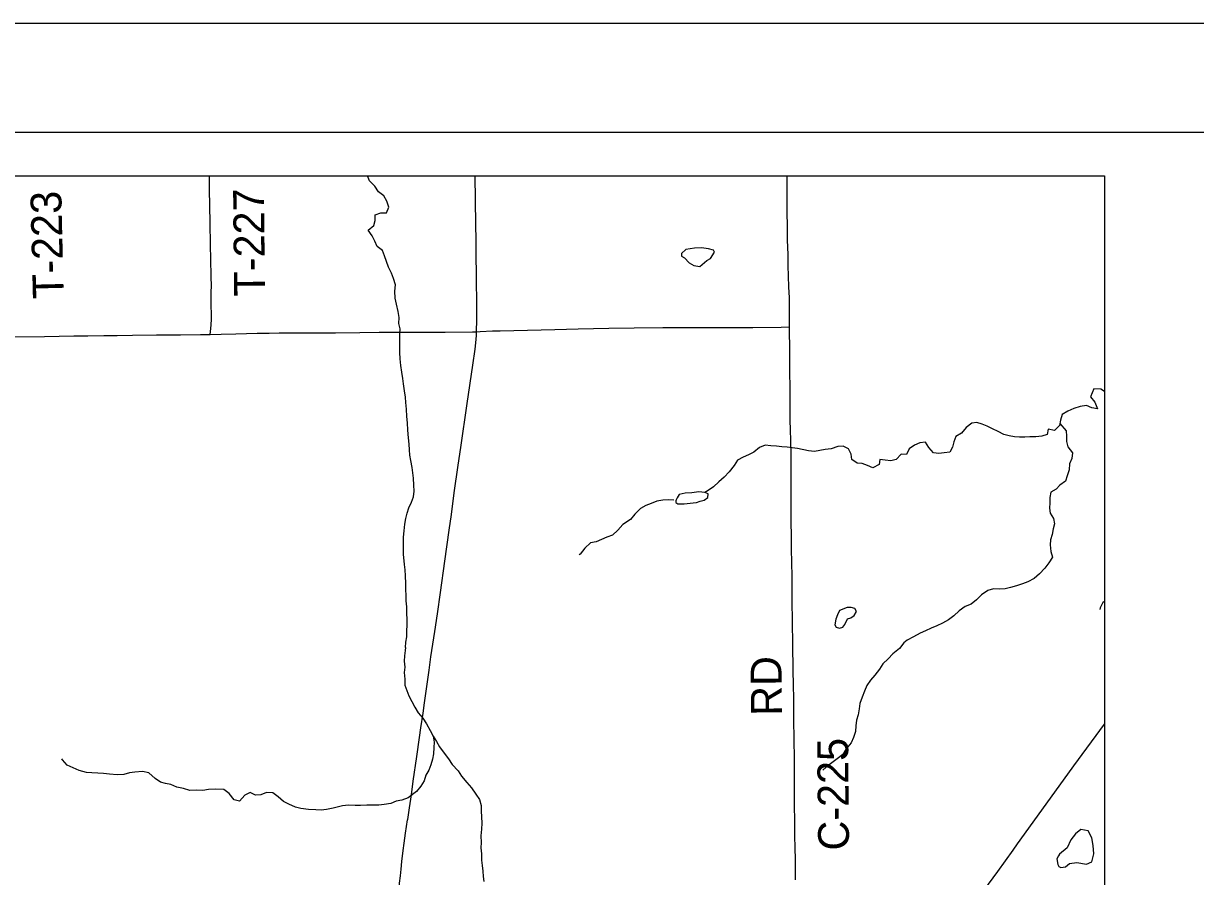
# Model space of a CAD drawing. Extents: x 0 to 34, y 0 to 22.
# Drawn here: x 13.7 to 19.09, y 18.08 to 22 of the extents above; entities that cross this region are included whole.
import ezdxf

# ---------------------------------------------------------------- set-up
doc = ezdxf.new("R2010")
doc.units = 0
for name, color, linetype in [('GM_X_County_Road', 7, 'Continuous'), ('GM_X_County_Road_Text', 7, 'Continuous'), ('GM_X_Minor_Lake', 7, 'Continuous'), ('GM_X_Minor_River', 7, 'Continuous'), ('GM_X_State_Route', 7, 'Continuous'), ('GM_X_Township_Road', 7, 'Continuous'), ('GM_X_Township_Road_Text', 7, 'Continuous'), ('SH_Border', 7, 'Continuous'), ('SH_Cut_Line', 7, 'Continuous'), ('SH_Text', 7, 'Continuous')]:
    doc.layers.add(name, color=color, linetype=linetype)

msp = doc.modelspace()

# ---------------------------------------------------------------- linework, layer by layer
at = {"layer": 'GM_X_County_Road'}
for points in [[(17.2229, 20.6048), (17.2225, 20.7377), (17.2203, 20.7889), (17.2177, 20.8865), (17.2166, 20.9377), (17.2146, 21.0029), (17.2126, 21.1958), (17.2123, 21.2549), (17.2117, 21.2991)], [(15.7844, 20.5828), (15.8012, 20.5841), (15.857, 20.5859), (15.8927, 20.5867), (16.1444, 20.5934), (16.2515, 20.5958), (16.3928, 20.5995), (16.5093, 20.6011), (16.6413, 20.6017), (16.719, 20.6015), (16.8278, 20.6021), (16.8945, 20.6018), (17.0546, 20.6022), (17.1851, 20.6042), (17.2229, 20.6048)], [(17.2505, 18.0622), (17.2503, 18.1617), (17.2489, 18.2036), (17.2481, 18.2704), (17.2459, 18.4677), (17.2458, 18.5065), (17.2463, 18.6104), (17.2447, 18.716), (17.2434, 18.7921), (17.2425, 18.9008), (17.2415, 18.9521), (17.2405, 19.0313), (17.2388, 19.14), (17.2371, 19.2534), (17.236, 19.342), (17.2347, 19.4646), (17.2346, 19.5143), (17.2327, 19.5904), (17.2306, 19.7611), (17.2312, 19.8154), (17.2309, 19.8496), (17.2309, 19.8899), (17.2305, 20.016), (17.2286, 20.0872), (17.2278, 20.1275), (17.2267, 20.1803), (17.2263, 20.2331), (17.2259, 20.3092), (17.2248, 20.4133), (17.2242, 20.4877), (17.2229, 20.6048)], [(13.6426, 20.5582), (13.6588, 20.5587), (13.7969, 20.5609), (13.9321, 20.5629), (13.9973, 20.5638), (14.0703, 20.5652), (14.1324, 20.5657), (14.2022, 20.567), (14.3125, 20.5687), (14.4228, 20.569), (14.5144, 20.5703), (14.5517, 20.5702), (14.5597, 20.5702)], [(14.5597, 20.5702), (14.6106, 20.5707), (14.6773, 20.5736), (14.7748, 20.5755), (14.8306, 20.5766), (14.8772, 20.5768), (14.9486, 20.5773), (15.0121, 20.5775), (15.0741, 20.5778), (15.1362, 20.5779), (15.2481, 20.5792), (15.3367, 20.5804), (15.3708, 20.5805), (15.4298, 20.58), (15.565, 20.5809), (15.6396, 20.581), (15.7659, 20.5825), (15.7844, 20.5828)]]:
    msp.add_lwpolyline(points, dxfattribs=at)
at = {"layer": 'GM_X_Minor_Lake'}
for p, q in [((16.7405, 20.9221), (16.7624, 20.8994)), ((16.739, 19.7912), (16.7807, 19.7962)), ((17.4778, 19.2361), (17.49, 19.2628))]:
    msp.add_line(p, q, dxfattribs=at)
for points in [[(16.7624, 20.8994), (16.7833, 20.8871), (16.8109, 20.8825), (16.8213, 20.8911), (16.843, 20.9102), (16.86, 20.9188), (16.8779, 20.9484), (16.8732, 20.9579), (16.8504, 20.9644), (16.819, 20.9681), (16.7858, 20.9669), (16.746, 20.9601), (16.7271, 20.9429), (16.7262, 20.9305), (16.7405, 20.9221)], [(16.7807, 19.7962), (16.7958, 19.7981), (16.812, 19.803), (16.8309, 19.8078), (16.8479, 19.8202), (16.8498, 19.8374), (16.8345, 19.8439), (16.807, 19.8457), (16.7738, 19.8417), (16.7435, 19.8397), (16.716, 19.8348), (16.7066, 19.8195), (16.7019, 19.81), (16.7009, 19.8053), (16.701, 19.7977), (16.7095, 19.791), (16.7295, 19.7911), (16.739, 19.7912)], [(17.49, 19.2628), (17.5051, 19.2676), (17.5212, 19.2772), (17.5306, 19.2963), (17.5239, 19.3105), (17.5068, 19.3151), (17.4888, 19.3141), (17.4537, 19.3006), (17.4443, 19.2806), (17.4368, 19.2616), (17.4313, 19.2349), (17.438, 19.2236), (17.4532, 19.2189), (17.4683, 19.2247), (17.4778, 19.2361)], [(18.4707, 18.1186), (18.4926, 18.1227), (18.5105, 18.1381), (18.5437, 18.1422), (18.5893, 18.1342), (18.6138, 18.1458), (18.623, 18.182), (18.6188, 18.2199), (18.6137, 18.255), (18.5972, 18.2881), (18.5621, 18.2934), (18.5376, 18.2742), (18.517, 18.2464), (18.5003, 18.2092), (18.4653, 18.1803)], [(18.4653, 18.1803), (18.4606, 18.1726), (18.4523, 18.1583), (18.4563, 18.1336), (18.4621, 18.1233), (18.4707, 18.1186)]]:
    msp.add_lwpolyline(points, dxfattribs=at)
at = {"layer": 'GM_X_Minor_River'}
for points in [[(15.4582, 19.131), (15.459, 19.1557), (15.4636, 19.1795), (15.4635, 19.2061), (15.4653, 19.2346), (15.4652, 19.2593), (15.4641, 19.2878), (15.463, 19.3182), (15.461, 19.3458), (15.4599, 19.3714), (15.4589, 19.3952), (15.4587, 19.4256), (15.4576, 19.4607), (15.4556, 19.4873), (15.4526, 19.513), (15.4486, 19.5595), (15.4476, 19.5842), (15.4484, 19.6146), (15.4483, 19.6384), (15.4519, 19.6669), (15.4547, 19.6973), (15.4593, 19.724), (15.4649, 19.7487), (15.4733, 19.7725), (15.4846, 19.7982), (15.4939, 19.823), (15.4967, 19.8496), (15.4965, 19.8771), (15.4945, 19.9094), (15.4915, 19.9332), (15.4876, 19.9579), (15.4818, 19.9902), (15.4779, 20.0148), (15.4759, 20.0395), (15.4748, 20.0661), (15.4718, 20.0946), (15.4688, 20.1298), (15.4668, 20.163), (15.4638, 20.1925), (15.4617, 20.2267), (15.4597, 20.2571), (15.4568, 20.2818), (15.4528, 20.3112), (15.4489, 20.3435), (15.4459, 20.3682), (15.441, 20.3967), (15.4362, 20.4271), (15.4332, 20.4584), (15.4312, 20.4869), (15.432, 20.5135), (15.4318, 20.543), (15.4308, 20.5724), (15.4326, 20.5962), (15.4267, 20.6209), (15.4285, 20.6475), (15.4237, 20.676), (15.4159, 20.7092), (15.4101, 20.7367), (15.409, 20.769), (15.4108, 20.7985), (15.403, 20.827), (15.3925, 20.8516), (15.38, 20.8791), (15.3695, 20.9057), (15.3608, 20.9313), (15.3522, 20.9559), (15.3274, 20.9748), (15.3169, 20.9995), (15.3044, 21.0241), (15.2863, 21.0488), (15.3118, 21.0707), (15.3174, 21.0945), (15.3182, 21.1202), (15.3448, 21.1298), (15.3694, 21.129), (15.3816, 21.1547), (15.372, 21.1822), (15.3577, 21.2069), (15.3339, 21.2257), (15.3167, 21.2513), (15.2919, 21.2759), (15.2829, 21.2991)], [(18.6712, 20.3073), (18.6546, 20.3178), (18.6224, 20.3194), (18.6075, 20.2832), (18.6266, 20.2586), (18.6392, 20.2283), (18.6136, 20.2329), (18.5888, 20.2441), (18.5595, 20.2391), (18.5302, 20.2293), (18.5027, 20.2177), (18.4773, 20.2023), (18.4699, 20.1766), (18.4653, 20.1518), (18.4418, 20.1279)], [(18.4418, 20.1279), (18.4121, 20.1341), (18.4084, 20.1103), (18.3838, 20.1016), (18.3553, 20.0996), (18.3288, 20.0994), (18.305, 20.0984), (18.2813, 20.0983), (18.2576, 20.1), (18.2329, 20.1037), (18.2082, 20.1093), (18.1825, 20.1244), (18.1559, 20.1356), (18.1321, 20.1479), (18.1084, 20.1582), (18.0846, 20.1657), (18.0609, 20.1618), (18.0354, 20.1417), (18.0137, 20.1169), (17.9881, 20.1015), (17.9787, 20.0768), (17.9732, 20.0521), (17.96, 20.0282), (17.9344, 20.0253), (17.9097, 20.0232), (17.885, 20.025), (17.8631, 20.0496), (17.8478, 20.0742), (17.8232, 20.0713), (17.7985, 20.0607), (17.7739, 20.0434), (17.7608, 20.0187), (17.737, 20.0195), (17.7134, 19.9956), (17.6888, 19.9889), (17.6632, 19.9916), (17.6385, 19.9953), (17.6348, 19.9715), (17.6064, 19.9571), (17.5817, 19.9674), (17.5579, 19.9759), (17.5342, 19.9786), (17.5104, 19.9946), (17.5074, 20.0193), (17.494, 20.044), (17.4693, 20.0562), (17.4456, 20.0542), (17.4143, 20.0445), (17.3878, 20.0415), (17.3631, 20.0357), (17.3375, 20.0318), (17.3109, 20.0345), (17.2597, 20.0456), (17.2359, 20.0493), (17.2122, 20.052), (17.1875, 20.0538), (17.1628, 20.0565), (17.1372, 20.0583), (17.1116, 20.061), (17.0851, 20.0495), (17.0595, 20.0285), (17.0349, 20.016), (17.0094, 20.0054), (16.9847, 19.992), (16.9687, 19.9682), (16.9461, 19.9386), (16.9225, 19.9137), (16.8979, 19.8927), (16.8733, 19.8688), (16.8487, 19.8526), (16.8346, 19.843)], [(18.4669, 20.1603), (18.4949, 20.1264), (18.497, 20.1027), (18.4963, 20.078), (18.5031, 20.0533), (18.5242, 20.025), (18.5215, 20.0003), (18.5113, 19.9745), (18.5087, 19.9479), (18.4994, 19.9203), (18.493, 19.8955), (18.4666, 19.8772), (18.4494, 19.8587)], [(18.4494, 19.8587), (18.4248, 19.8452), (18.4202, 19.8196), (18.4203, 19.7958), (18.4185, 19.772), (18.4224, 19.7483), (18.4367, 19.7237), (18.4416, 19.6999), (18.436, 19.6762), (18.4314, 19.6505), (18.4239, 19.6257), (18.4211, 19.602), (18.4251, 19.5716), (18.4318, 19.5459), (18.4158, 19.5202), (18.397, 19.4954), (18.3734, 19.4687), (18.3488, 19.4476), (18.3194, 19.4332), (18.2948, 19.4236), (18.2664, 19.4149), (18.2399, 19.4062), (18.2152, 19.4004), (18.1867, 19.3993), (18.1611, 19.4001), (18.1346, 19.3934), (18.1062, 19.3733), (18.0826, 19.3494), (18.058, 19.3293), (18.0306, 19.3187), (18.0031, 19.2986), (17.9786, 19.2766), (17.954, 19.2585), (17.9265, 19.2422), (17.9, 19.2297), (17.8744, 19.2191), (17.8489, 19.2076), (17.8243, 19.196), (17.793, 19.1797), (17.7646, 19.1639)], [(16.6914, 19.8081), (16.6658, 19.8089), (16.6411, 19.8078), (16.6137, 19.8029), (16.5871, 19.7923), (16.5625, 19.7837), (16.5379, 19.7693), (16.5114, 19.7444), (16.4916, 19.7196), (16.4576, 19.6957), (16.434, 19.6709), (16.4094, 19.6479), (16.3838, 19.6383), (16.3583, 19.6268), (16.3336, 19.6162), (16.308, 19.6123), (16.2825, 19.5874), (16.2599, 19.5598), (16.2561, 19.556)], [(18.6712, 19.3373), (18.6652, 19.3401), (18.6512, 19.3134), (18.6503, 19.3048)], [(17.7646, 19.1639), (17.7491, 19.1527), (17.7286, 19.1259), (17.6985, 19.1018), (17.6761, 19.0778), (17.6517, 19.0557), (17.6368, 19.0308), (17.6154, 19.004), (17.5957, 18.98), (17.579, 18.9552), (17.5679, 18.9294), (17.5568, 18.9017), (17.5467, 18.8731), (17.5432, 18.8484), (17.5388, 18.8218), (17.5315, 18.797), (17.5289, 18.7704), (17.5264, 18.7447), (17.5172, 18.7161), (17.5061, 18.6923), (17.4837, 18.6654), (17.4679, 18.6387), (17.4416, 18.6184), (17.4172, 18.6001), (17.3919, 18.5799), (17.3769, 18.5664)], [(15.4582, 19.131), (15.4562, 19.1174), (15.4527, 19.0919), (15.4511, 19.0672), (15.4542, 19.0406), (15.4516, 19.015), (15.4548, 18.9846), (15.4551, 18.958), (15.463, 18.9334), (15.4736, 18.9089), (15.4872, 18.8825), (15.4998, 18.856), (15.5152, 18.8296), (15.5373, 18.8052), (15.5546, 18.7798), (15.571, 18.7496), (15.5855, 18.7232), (15.6, 18.6986), (15.6145, 18.6732), (15.6356, 18.6449), (15.6549, 18.6195), (15.6722, 18.5931), (15.699, 18.564), (15.7145, 18.5395), (15.7394, 18.5104), (15.7615, 18.485), (15.7807, 18.4567), (15.7971, 18.4322), (15.805, 18.4038), (15.8062, 18.3782), (15.8065, 18.3526), (15.8087, 18.3232), (15.8071, 18.2956), (15.8046, 18.2643), (15.805, 18.2339), (15.8043, 18.2092), (15.8065, 18.1826), (15.8077, 18.1532), (15.8099, 18.1276), (15.813, 18.102), (15.8152, 18.0783), (15.8183, 18.0546)], [(15.5855, 18.7232), (15.5896, 18.6957), (15.588, 18.671), (15.5864, 18.6415), (15.581, 18.6177), (15.5747, 18.5911), (15.5655, 18.5672), (15.5516, 18.5433), (15.5433, 18.5176), (15.5275, 18.4937), (15.5079, 18.4678), (15.4703, 18.4398), (15.4401, 18.429), (15.4146, 18.424), (15.3901, 18.4133), (15.3589, 18.4082), (15.3343, 18.406), (15.3088, 18.4057), (15.2794, 18.4063), (15.251, 18.4041), (15.2264, 18.4047), (15.1952, 18.4053), (15.1677, 18.4021), (15.1252, 18.3922), (15.095, 18.3861), (15.0704, 18.383), (15.0458, 18.3846), (15.0117, 18.3851), (14.9766, 18.3904), (14.9519, 18.3968), (14.9205, 18.4097), (14.8967, 18.4227), (14.8728, 18.4443), (14.847, 18.462), (14.8186, 18.4645), (14.7922, 18.4538), (14.7676, 18.4516), (14.7438, 18.4637), (14.7184, 18.451), (14.695, 18.4242), (14.6694, 18.4305), (14.6463, 18.4597), (14.6225, 18.4775), (14.5827, 18.4789), (14.5524, 18.4776), (14.525, 18.4735), (14.4984, 18.4751), (14.4653, 18.4737), (14.4368, 18.4829), (14.4065, 18.4882), (14.3789, 18.5003), (14.3542, 18.5057), (14.3304, 18.512), (14.3066, 18.5279), (14.2769, 18.5551), (14.2485, 18.5605), (14.2135, 18.5572), (14.1879, 18.5541), (14.1625, 18.5471), (14.1312, 18.5458), (14.0971, 18.5483), (14.0687, 18.5508), (14.0422, 18.5524), (14.0147, 18.5539), (13.991, 18.5565), (13.9577, 18.5656), (13.9292, 18.5776), (13.9016, 18.5897), (13.8805, 18.6141), (13.8776, 18.6188)]]:
    msp.add_lwpolyline(points, dxfattribs=at)
at = {"layer": 'GM_X_State_Route'}
for points in [[(15.4675, 18.3404), (15.4757, 18.3933), (15.4845, 18.4532), (15.4932, 18.5163), (15.51, 18.6301), (15.5219, 18.7163), (15.5283, 18.7609), (15.538, 18.8286), (15.5448, 18.8763), (15.5665, 19.0271), (15.5744, 19.0872), (15.592, 19.204), (15.604, 19.2855), (15.6183, 19.3839), (15.6388, 19.527), (15.658, 19.6702), (15.6683, 19.7426), (15.6819, 19.8411), (15.6998, 19.9689), (15.7119, 20.0503), (15.7414, 20.2518), (15.7675, 20.4286), (15.7773, 20.5026), (15.7821, 20.5473), (15.7836, 20.5674), (15.7844, 20.5828), (15.7846, 20.5875), (15.7855, 20.6325), (15.7853, 20.707), (15.7839, 20.8267), (15.7826, 20.9511), (15.7823, 21.0039), (15.7815, 21.0754), (15.7777, 21.2991)], [(18.2511, 18.1988), (18.2716, 18.2273), (18.4036, 18.4099), (18.5312, 18.5861), (18.6712, 18.7786)], [(15.4253, 17.6106), (15.4249, 17.6255), (15.4244, 17.6845), (15.4231, 17.7357), (15.4222, 17.7932), (15.4218, 17.8414), (15.4221, 17.885), (15.4231, 17.9126), (15.4238, 17.9332), (15.4244, 17.9442), (15.4272, 18), (15.4305, 18.0465), (15.4338, 18.0806), (15.437, 18.1115), (15.4405, 18.1471), (15.4466, 18.198), (15.4511, 18.2303), (15.4581, 18.2764), (15.4671, 18.338), (15.4675, 18.3404)], [(17.9736, 17.8144), (17.9942, 17.843), (18.0187, 17.877), (18.0616, 17.9363), (18.1166, 18.0127), (18.1805, 18.1014), (18.2511, 18.1988)]]:
    msp.add_lwpolyline(points, dxfattribs=at)
at = {"layer": 'GM_X_Township_Road'}
msp.add_lwpolyline([(14.5597, 20.5702), (14.5625, 20.5978), (14.5641, 20.6147), (14.5651, 20.6408), (14.5649, 20.6609), (14.5646, 20.7058), (14.5645, 20.7661), (14.565, 20.7923), (14.5636, 20.837), (14.563, 20.916), (14.5616, 20.9799), (14.5593, 21.0843), (14.5564, 21.236), (14.556, 21.2563), (14.5559, 21.2991)], dxfattribs=at)
at = {"layer": 'SH_Border'}
msp.add_lwpolyline([(1.5, 21.5), (33.5, 21.5), (33.5, 0.5), (1.5, 0.5)], close=True, dxfattribs=at)
at = {"layer": 'SH_Cut_Line'}
msp.add_lwpolyline([(0, 0), (34, 0), (34, 22), (0, 22)], close=True, dxfattribs=at)
at = {"layer": 'SH_Text'}
msp.add_lwpolyline([(1.6712, 21.2991), (18.6712, 21.2991), (18.6712, 4.2991), (1.6712, 4.2991)], close=True, dxfattribs=at)

# ---------------------------------------------------------------- texts
at = {"layer": 'GM_X_County_Road_Text'}
for s, rotation, p in [('RD', 90.4884, (17.1884, 18.8172)), ('C-225', 90.5469, (17.4973, 18.1978))]:
    msp.add_text(s, height=0.14205, rotation=rotation, dxfattribs=at).set_placement(p)
at = {"layer": 'GM_X_Township_Road_Text'}
for s, rotation, p in [('T-223', 91.3901, (13.8865, 20.7354)), ('T-227', 90.5575, (14.8116, 20.7457))]:
    msp.add_text(s, height=0.14205, rotation=rotation, dxfattribs=at).set_placement(p)

doc.saveas('drawing.dxf')
